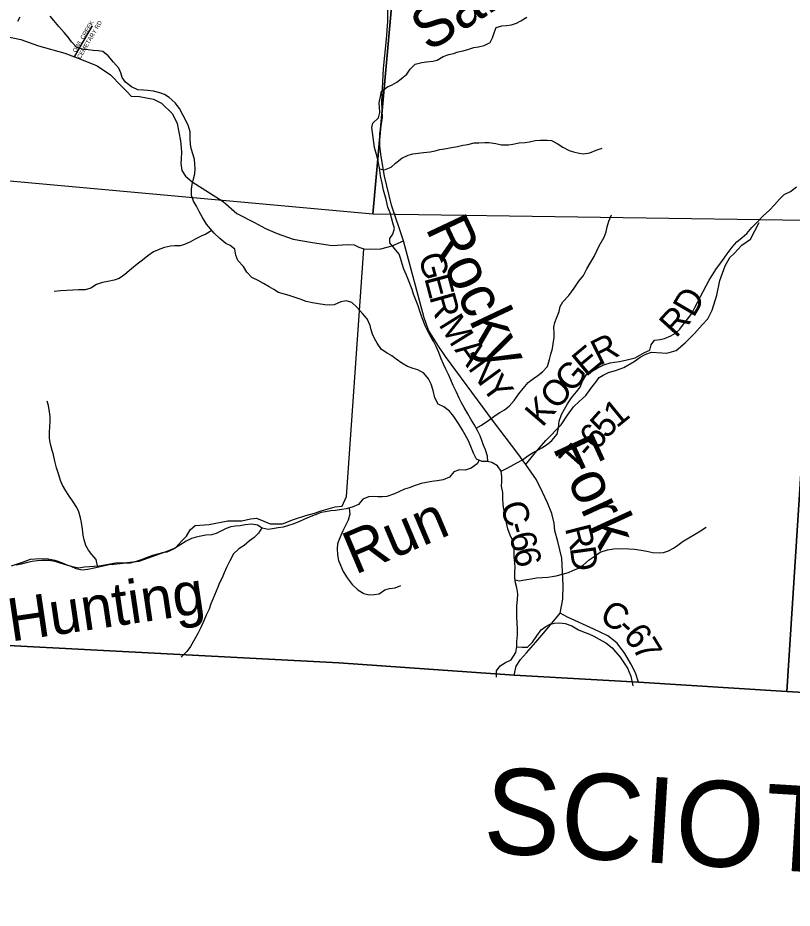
# Model space of a CAD drawing. Extents: x 1578669 to 1989827, y 208020 to 553079.
# Drawn here: x 1851077 to 1860103, y 344278 to 354659 of the extents above; entities that cross this region are included whole.
import ezdxf

# ---------------------------------------------------------------- set-up
doc = ezdxf.new("R2010")
doc.units = 0
for name, color, linetype in [('GM_X_Adjacent_County', 7, 'Continuous'), ('GM_X_Adjacent_County_Text', 7, 'Continuous'), ('GM_X_County', 7, 'Continuous'), ('GM_X_County_Road', 7, 'Continuous'), ('GM_X_County_Road_Text', 7, 'Continuous'), ('GM_X_Minor_River', 7, 'Continuous'), ('GM_X_Minor_River_Text', 7, 'Continuous'), ('GM_X_Section', 7, 'Continuous'), ('GM_X_Township', 7, 'Continuous'), ('GM_X_Township_Road', 7, 'Continuous'), ('GM_X_Township_Road_Text', 7, 'Continuous'), ('GM_X_Township_Subdivision', 7, 'Continuous'), ('GM_X_Township_Subdivision_Text', 7, 'Continuous')]:
    doc.layers.add(name, color=color, linetype=linetype)

msp = doc.modelspace()

# ---------------------------------------------------------------- linework, layer by layer
at = {"layer": 'GM_X_Adjacent_County'}
msp.add_lwpolyline([(1795056, 349285), (1813587, 349087), (1813935, 349079), (1818598, 348960), (1819510, 348957), (1826336, 348649), (1831370, 348458), (1833224, 348359), (1833481, 348350), (1833762, 348331), (1834882, 348273), (1835528, 348231), (1838968, 348044), (1844797, 347685), (1845155, 347665), (1846968, 347563), (1848416, 347480), (1849999, 347391), (1854820, 347140), (1856863, 346996), (1858312, 346913), (1860040, 346806), (1865771, 346465)], dxfattribs=at)
at = {"layer": 'GM_X_County'}
msp.add_lwpolyline([(1865771, 346465), (1860040, 346806), (1858312, 346913), (1856863, 346996), (1854820, 347140), (1849999, 347391), (1848416, 347480), (1846968, 347563), (1845155, 347665), (1844797, 347685), (1838968, 348044), (1835528, 348231), (1834882, 348273), (1833762, 348331), (1833481, 348350), (1833224, 348359), (1831370, 348458), (1826336, 348649), (1819510, 348957), (1818598, 348960), (1813935, 349079), (1813587, 349087), (1795056, 349285)], dxfattribs=at)
at = {"layer": 'GM_X_County_Road'}
for points in [[(1857398, 347719), (1857431, 347880), (1857432, 348039), (1857427, 348199), (1857419, 348360), (1857370, 348553), (1857335, 348677), (1857329, 348768), (1857302, 348880), (1857252, 349005), (1857193, 349129), (1857121, 349272), (1857000, 349450), (1856904, 349579), (1856620, 349951), (1856064, 350711), (1855973, 350842), (1855865, 351019), (1855814, 351160), (1855572, 352058), (1855432, 352474), (1855353, 352812), (1855312, 353041), (1855297, 353161), (1855296, 353312), (1855329, 353494), (1855322, 353679), (1855340, 354070), (1855374, 354411), (1855389, 354618), (1855391, 354752)], [(1850927, 354444), (1851114, 354405), (1851320, 354333), (1851626, 354249), (1851738, 354205), (1851820, 354172), (1852004, 354101), (1852156, 353996), (1852282, 353868), (1852349, 353800), (1852399, 353747), (1852497, 353743), (1852660, 353710), (1852752, 353663), (1852881, 353538), (1852933, 353429), (1852972, 353224), (1852987, 353098), (1852981, 353010), (1852977, 352962), (1852990, 352879), (1853032, 352813), (1853108, 352746), (1853471, 352519), (1853631, 352376), (1853837, 352273), (1853963, 352204), (1854101, 352145), (1854285, 352077), (1854513, 352038), (1854740, 352005), (1854920, 352018), (1854996, 352013), (1855052, 351987), (1855112, 351964), (1855193, 351960), (1855307, 351967), (1855439, 351999), (1855572, 352058)], [(1851004, 348269), (1851133, 348314), (1851227, 348348), (1851337, 348355), (1851432, 348351), (1851510, 348336), (1851588, 348310), (1851650, 348283), (1851698, 348265), (1851786, 348245), (1851854, 348258), (1852026, 348271), (1852221, 348306), (1852351, 348310), (1852490, 348325), (1852805, 348438), (1852914, 348481), (1852986, 348559), (1853043, 348617), (1853085, 348691), (1853145, 348739), (1853306, 348750), (1853525, 348793), (1853687, 348796), (1853789, 348819), (1853858, 348825), (1853946, 348792), (1854020, 348758), (1854162, 348761), (1854289, 348811), (1854433, 348856), (1854537, 348885), (1854614, 348909), (1854776, 348956), (1854857, 348966), (1854909, 349078), (1855112, 351964)], [(1856863, 346996), (1856884, 347098), (1856938, 347176), (1857007, 347257), (1857115, 347379), (1857210, 347490), (1857398, 347719)], [(1858312, 346913), (1858275, 347024), (1858223, 347127), (1858151, 347247), (1858062, 347368), (1857955, 347453), (1857791, 347533), (1857486, 347672), (1857398, 347719)]]:
    msp.add_lwpolyline(points, dxfattribs=at)
at = {"layer": 'GM_X_Minor_River'}
for points in [[(1851102, 354668), (1851073, 354616)], [(1853501, 352029), (1853432, 352085), (1853364, 352148), (1853278, 352254), (1853229, 352333), (1853192, 352400), (1853159, 352465), (1853124, 352520), (1853102, 352588), (1853101, 352662), (1853110, 352714), (1853123, 352768), (1853139, 352840), (1853144, 352898), (1853141, 352954), (1853138, 353008), (1853123, 353063), (1853098, 353137), (1853089, 353188), (1853087, 353254), (1853086, 353328), (1853065, 353395), (1853040, 353453), (1853006, 353520), (1852963, 353601), (1852912, 353668), (1852842, 353730), (1852786, 353767), (1852731, 353786), (1852659, 353805), (1852593, 353813), (1852541, 353814), (1852475, 353821), (1852404, 353854), (1852333, 353910), (1852292, 353965), (1852279, 354017), (1852254, 354072), (1852193, 354143), (1852130, 354217), (1852067, 354266), (1852015, 354275), (1851955, 354278), (1851899, 354285), (1851831, 354295), (1851770, 354310), (1851703, 354379), (1851664, 354434), (1851617, 354487), (1851554, 354559), (1851498, 354628), (1851454, 354679)], [(1856554, 349487), (1856551, 349548), (1856528, 349623), (1856505, 349675), (1856484, 349732), (1856467, 349784), (1856436, 349847), (1856397, 349916), (1856359, 349981), (1856324, 350040), (1856279, 350117), (1856250, 350169), (1856221, 350226), (1856189, 350295), (1856152, 350374), (1856123, 350440), (1856098, 350499), (1856066, 350564), (1856037, 350622), (1856012, 350683), (1855983, 350758), (1855953, 350826), (1855922, 350889), (1855885, 350954), (1855854, 351015), (1855825, 351069), (1855800, 351130), (1855781, 351181), (1855762, 351239), (1855742, 351300), (1855721, 351358), (1855690, 351439), (1855673, 351491), (1855631, 351600), (1855606, 351659), (1855578, 351730), (1855559, 351790), (1855540, 351845), (1855521, 351903), (1855466, 351968), (1855415, 352035), (1855414, 352086), (1855447, 352137), (1855469, 352201), (1855448, 352269), (1855431, 352326), (1855416, 352386), (1855391, 352453), (1855369, 352541), (1855354, 352594), (1855339, 352648), (1855323, 352733), (1855306, 352815), (1855292, 352910), (1855283, 352966), (1855270, 353022), (1855252, 353091), (1855235, 353147), (1855228, 353204), (1855219, 353264), (1855210, 353322), (1855205, 353380), (1855216, 353432), (1855281, 353493), (1855297, 353557), (1855292, 353617), (1855291, 353669), (1855304, 353741), (1855317, 353805), (1855386, 353856), (1855439, 353879), (1855496, 353910), (1855546, 353947), (1855613, 354004), (1855651, 354059), (1855710, 354120), (1855786, 354140), (1855842, 354147), (1855915, 354154), (1855967, 354165), (1856036, 354208), (1856102, 354230), (1856155, 354245), (1856211, 354262), (1856267, 354273), (1856336, 354294), (1856394, 354313), (1856446, 354322), (1856513, 354337), (1856581, 354371), (1856609, 354425), (1856628, 354483), (1856651, 354548), (1856717, 354565), (1856772, 354570), (1856832, 354579), (1856888, 354596), (1856941, 354623), (1857010, 354665)], [(1855294, 352899), (1855350, 352886), (1855428, 352919), (1855479, 352964), (1855554, 353021), (1855627, 353057), (1855680, 353074), (1855744, 353083), (1855806, 353090), (1855882, 353096), (1855943, 353109), (1855997, 353124), (1856049, 353133), (1856131, 353148), (1856202, 353158), (1856266, 353173), (1856322, 353184), (1856395, 353201), (1856449, 353203), (1856519, 353206), (1856569, 353205), (1856649, 353194), (1856715, 353180), (1856795, 353179), (1856847, 353186), (1856919, 353200), (1856989, 353207), (1857042, 353212), (1857108, 353227), (1857166, 353233), (1857246, 353234), (1857298, 353229), (1857362, 353193), (1857431, 353150), (1857502, 353111), (1857556, 353097), (1857620, 353080), (1857672, 353073), (1857746, 353086), (1857819, 353116), (1857887, 353139)], [(1856711, 349373), (1856772, 349403), (1856825, 349432), (1856895, 349469), (1856958, 349504), (1857023, 349551), (1857078, 349588), (1857132, 349615), (1857185, 349644), (1857250, 349689), (1857301, 349730), (1857364, 349803), (1857378, 349880), (1857387, 349958), (1857413, 350034), (1857448, 350096), (1857483, 350157), (1857529, 350228), (1857588, 350299), (1857633, 350354), (1857660, 350424), (1857704, 350499), (1857757, 350532), (1857830, 350575), (1857908, 350615), (1857981, 350636), (1858031, 350643), (1858089, 350654), (1858142, 350663), (1858196, 350674), (1858272, 350696), (1858329, 350725), (1858382, 350758), (1858442, 350785), (1858459, 350845), (1858497, 350902), (1858563, 350907), (1858613, 350920), (1858688, 350953), (1858742, 350984), (1858795, 351031), (1858836, 351086), (1858898, 351167), (1858939, 351220), (1858970, 351280), (1859002, 351349), (1859029, 351403), (1859064, 351468), (1859105, 351542), (1859137, 351599), (1859176, 351663), (1859221, 351736), (1859271, 351803), (1859310, 351856), (1859347, 351908), (1859404, 351985), (1859459, 352046), (1859521, 352097), (1859573, 352144), (1859633, 352213), (1859692, 352274), (1859764, 352350), (1859837, 352417), (1859896, 352478), (1859954, 352545), (1860011, 352598), (1860085, 352635), (1860155, 352687)], [(1856421, 349875), (1856483, 349910), (1856567, 349967), (1856642, 350021), (1856695, 350058), (1856749, 350089), (1856806, 350132), (1856861, 350197), (1856917, 350274), (1856968, 350337), (1857026, 350408), (1857087, 350455), (1857137, 350490), (1857194, 350533), (1857253, 350592), (1857273, 350676), (1857290, 350738), (1857309, 350804), (1857319, 350860), (1857328, 350932), (1857329, 350982), (1857324, 351052), (1857337, 351106), (1857365, 351177), (1857386, 351237), (1857397, 351295), (1857430, 351346), (1857498, 351423), (1857563, 351506), (1857617, 351589), (1857670, 351654), (1857710, 351732), (1857749, 351797), (1857795, 351878), (1857828, 351942), (1857855, 351999), (1857913, 352102), (1857936, 352164), (1857945, 352222), (1857965, 352288), (1857998, 352361)], [(1853337, 352181), (1853267, 352138), (1853213, 352113), (1853144, 352078), (1853089, 352047), (1853021, 352015), (1852970, 352002), (1852908, 351999), (1852856, 351996), (1852788, 351983), (1852731, 351960), (1852659, 351930), (1852592, 351885), (1852529, 351834), (1852470, 351787), (1852403, 351734), (1852325, 351668), (1852260, 351621), (1852202, 351600), (1852127, 351583), (1852065, 351572), (1851993, 351548), (1851928, 351507), (1851861, 351486), (1851785, 351488), (1851719, 351485), (1851649, 351478), (1851573, 351476), (1851501, 351467)], [(1856656, 346973), (1856656, 347044), (1856698, 347104), (1856760, 347141), (1856827, 347172), (1856883, 347259), (1856894, 347331), (1856895, 347387), (1856901, 347467), (1856900, 347533), (1856897, 347605), (1856895, 347670), (1856892, 347742), (1856895, 347802), (1856901, 347876), (1856904, 347944), (1856895, 348012), (1856880, 348071), (1856870, 348131), (1856871, 348199), (1856874, 348249), (1856869, 348303), (1856864, 348374), (1856863, 348424), (1856863, 348494), (1856848, 348560), (1856815, 348627), (1856790, 348702), (1856774, 348770), (1856761, 348821), (1856756, 348871), (1856743, 348929), (1856734, 348985), (1856731, 349054), (1856729, 349124), (1856714, 349200), (1856717, 349252), (1856720, 349306), (1856711, 349373), (1856670, 349436), (1856603, 349475), (1856551, 349488), (1856491, 349485), (1856424, 349515), (1856387, 349585), (1856357, 349662), (1856330, 349729), (1856291, 349798), (1856258, 349858), (1856214, 349930), (1856159, 350009), (1856108, 350072), (1856041, 350123), (1855978, 350155), (1855937, 350230), (1855917, 350314), (1855896, 350387), (1855865, 350449), (1855808, 350517), (1855739, 350556), (1855685, 350569), (1855620, 350593), (1855554, 350632), (1855487, 350681), (1855436, 350720), (1855383, 350750), (1855315, 350793), (1855265, 350864), (1855234, 350919), (1855213, 350969), (1855196, 351022), (1855183, 351072), (1855148, 351149), (1855095, 351212), (1855029, 351284), (1854970, 351341), (1854906, 351360), (1854842, 351347), (1854765, 351311), (1854709, 351308), (1854657, 351313), (1854581, 351326), (1854513, 351336), (1854439, 351353), (1854368, 351379), (1854310, 351400), (1854250, 351419), (1854187, 351436), (1854117, 351456), (1854060, 351491), (1854008, 351522), (1853941, 351560), (1853879, 351597), (1853804, 351632), (1853747, 351692), (1853708, 351761), (1853642, 351830), (1853617, 351893), (1853606, 351961), (1853553, 352004), (1853501, 352029)], [(1852010, 348252), (1851989, 348342), (1851940, 348401), (1851901, 348454), (1851870, 348506), (1851851, 348571), (1851840, 348627), (1851830, 348697), (1851821, 348774), (1851808, 348828), (1851787, 348899), (1851764, 348951), (1851724, 349014), (1851671, 349091), (1851638, 349144), (1851599, 349209), (1851574, 349264), (1851554, 349332), (1851527, 349411), (1851507, 349491), (1851494, 349562), (1851475, 349628), (1851460, 349687), (1851448, 349753), (1851447, 349823), (1851450, 349893), (1851455, 349949), (1851455, 350011), (1851448, 350066), (1851435, 350140), (1851420, 350190)], [(1856453, 349502), (1856431, 349458), (1856362, 349410), (1856291, 349385), (1856225, 349388), (1856161, 349367), (1856107, 349304), (1856035, 349272), (1855966, 349261), (1855904, 349254), (1855840, 349243), (1855780, 349229), (1855709, 349206), (1855637, 349179), (1855586, 349164), (1855520, 349134), (1855467, 349111), (1855378, 349080), (1855328, 349073), (1855274, 349076), (1855222, 349077), (1855166, 349074), (1855099, 349048), (1855048, 348985), (1854976, 348952), (1854905, 348935), (1854855, 348926), (1854779, 348916), (1854726, 348909), (1854664, 348900), (1854614, 348893), (1854543, 348866), (1854475, 348836), (1854420, 348813), (1854352, 348782), (1854281, 348757), (1854231, 348740), (1854170, 348719), (1854112, 348712), (1854044, 348702), (1853994, 348695), (1853926, 348708), (1853870, 348743), (1853803, 348757), (1853728, 348748), (1853670, 348735), (1853612, 348732), (1853560, 348725), (1853505, 348706), (1853453, 348679), (1853390, 348645), (1853336, 348630), (1853268, 348627), (1853211, 348616), (1853155, 348603), (1853103, 348588), (1853038, 348557), (1852967, 348509), (1852886, 348460), (1852815, 348429), (1852763, 348420), (1852707, 348404), (1852648, 348389), (1852584, 348366), (1852515, 348339), (1852457, 348320), (1852386, 348300), (1852336, 348299), (1852270, 348294), (1852196, 348287), (1852142, 348280), (1852086, 348270), (1852021, 348255), (1851967, 348242), (1851893, 348227), (1851824, 348219), (1851759, 348236), (1851701, 348261), (1851649, 348278), (1851572, 348302), (1851514, 348319), (1851440, 348330), (1851360, 348332), (1851302, 348329), (1851244, 348320), (1851192, 348309), (1851115, 348291), (1851057, 348278)], [(1854939, 348943), (1854946, 348872), (1854929, 348803), (1854891, 348733), (1854866, 348678), (1854831, 348598), (1854803, 348528), (1854798, 348468), (1854803, 348396), (1854815, 348332), (1854838, 348277), (1854869, 348203), (1854916, 348128), (1854976, 348052), (1855039, 347989), (1855110, 347949), (1855174, 347932), (1855232, 347935), (1855288, 347944), (1855355, 347989), (1855410, 348004), (1855476, 348014), (1855543, 348041)], [(1856874, 348106), (1856921, 348096), (1856987, 348107), (1857059, 348119), (1857124, 348130), (1857190, 348135), (1857254, 348139), (1857304, 348144), (1857354, 348152), (1857427, 348174), (1857495, 348193), (1857546, 348214), (1857614, 348243), (1857669, 348280), (1857736, 348340), (1857807, 348387), (1857866, 348428), (1857951, 348458), (1858025, 348469), (1858081, 348470), (1858199, 348467), (1858265, 348464), (1858341, 348451), (1858407, 348439), (1858477, 348426), (1858551, 348420), (1858605, 348427), (1858661, 348446), (1858718, 348477), (1858769, 348512), (1858834, 348557), (1858898, 348596), (1858965, 348635), (1859034, 348677), (1859101, 348722)], [(1853920, 348712), (1853881, 348651), (1853832, 348600), (1853779, 348561), (1853716, 348508), (1853653, 348467), (1853592, 348410), (1853550, 348329), (1853509, 348251), (1853483, 348188), (1853458, 348130), (1853429, 348073), (1853408, 348019), (1853349, 347880), (1853328, 347826), (1853309, 347766), (1853274, 347693), (1853244, 347629), (1853209, 347552), (1853175, 347479), (1853140, 347417), (1853090, 347328), (1853047, 347271), (1852982, 347205)], [(1856893, 347325), (1856954, 347322), (1857018, 347323), (1857077, 347379), (1857125, 347453), (1857176, 347522), (1857233, 347563), (1857283, 347588), (1857334, 347601), (1857386, 347604), (1857456, 347596), (1857533, 347569), (1857613, 347523), (1857678, 347496), (1857732, 347475), (1857791, 347450), (1857855, 347416), (1857932, 347371), (1858005, 347313), (1858046, 347262), (1858099, 347203), (1858136, 347148), (1858182, 347077), (1858224, 346983), (1858244, 346872)]]:
    msp.add_lwpolyline(points, dxfattribs=at)
at = {"layer": 'GM_X_Section'}
for points in [[(1850307, 358069), (1855700, 357766), (1855214, 352368), (1849954, 352849)], [(1855700, 357766), (1860738, 357233), (1860524, 352292), (1855214, 352368)]]:
    msp.add_lwpolyline(points, close=True, dxfattribs=at)
at = {"layer": 'GM_X_Township'}
for points in [[(1860651, 356303), (1860040, 346806), (1858312, 346913), (1856863, 346996), (1854820, 347140), (1849999, 347391), (1848416, 347480), (1846968, 347563), (1845155, 347665), (1844797, 347685), (1838968, 348044), (1839041, 349111), (1839441, 357011), (1839540, 358655), (1839593, 359479), (1839780, 362417), (1840250, 369801)], [(1865771, 346465), (1860040, 346806), (1860651, 356303)]]:
    msp.add_lwpolyline(points, dxfattribs=at)
at = {"layer": 'GM_X_Township_Road'}
msp.add_lwpolyline([(1857000, 349450), (1857107, 349587), (1857232, 349731), (1857411, 349913), (1857486, 350025), (1857555, 350125), (1857621, 350185), (1857696, 350256), (1857766, 350354), (1857813, 350410), (1857853, 350466), (1857899, 350492), (1857962, 350522), (1858056, 350551), (1858141, 350583), (1858261, 350653), (1858332, 350704), (1858396, 350738), (1858464, 350762), (1858584, 350753), (1858643, 350751), (1858749, 350782), (1858856, 350868), (1858966, 350980), (1859053, 351080), (1859118, 351151), (1859172, 351252), (1859225, 351424), (1859258, 351596), (1859323, 351766), (1859376, 351866), (1859426, 351910), (1859515, 352008), (1859618, 352080), (1859719, 352272)], dxfattribs=at)
at = {"layer": 'GM_X_Township_Subdivision'}
msp.add_lwpolyline([(1851738, 354205), (1851946, 354564)], dxfattribs=at)

# ---------------------------------------------------------------- texts
at = {"layer": 'GM_X_Adjacent_County_Text'}
msp.add_text('SCIOTO COUNTY', height=1000, rotation=356.533, dxfattribs=at).set_placement((1856488, 344929))
at = {"layer": 'GM_X_County_Road_Text'}
for s, rotation, p in [('G', 284.9781, (1855745, 351881)), ('E', 284.9816, (1855813, 351626)), ('R', 285.5173, (1855872, 351407)), ('M', 301.8274, (1855975, 351084)), ('A', 306.2088, (1856161, 350787)), ('N', 306.1297, (1856317, 350574)), ('Y', 306.1217, (1856472, 350361)), ('C', 286.3721, (1856698, 348979)), ('-', 286.1213, (1856767, 348743)), ('R', 284.2597, (1857452, 348709)), ('6', 285.3149, (1856801, 348626)), ('6', 283.1666, (1856849, 348450)), ('D', 277.7978, (1857511, 348479)), ('C', 330.8127, (1857841, 347629)), ('-', 317.6936, (1858040, 347521)), ('6', 309.3089, (1858122, 347447)), ('7', 301.2944, (1858232, 347314))]:
    msp.add_text(s, height=300, rotation=rotation, dxfattribs=at).set_placement(p)
at = {"layer": 'GM_X_Minor_River_Text'}
for s, rotation, p in [('Sand', 32.382, (1855866, 354254)), ('Rocky', 295.2863, (1855824, 352207)), ('Fork', 294.6859, (1857305, 349649)), ('Run', 22.9198, (1855008, 348163)), ('Hunting', 8.4088, (1850999, 347386))]:
    msp.add_text(s, height=500, rotation=rotation, dxfattribs=at).set_placement(p)
at = {"layer": 'GM_X_Township_Road_Text'}
for s, rotation, p in [('D', 59.6957, (1858954, 351154)), ('R', 47.7499, (1858748, 350917)), ('R', 26.6733, (1857855, 350600)), ('E', 39.8659, (1857698, 350466)), ('G', 49.0629, (1857534, 350275)), ('O', 49.2525, (1857362, 350076)), ('K', 49.2462, (1857190, 349876)), ('1', 39.2978, (1858058, 349869)), ('5', 47.9524, (1857943, 349740)), ('6', 50.3211, (1857827, 349601)), ('T', 48.4597, (1857591, 349332)), ('-', 49.146, (1857742, 349502))]:
    msp.add_text(s, height=300, rotation=rotation, dxfattribs=at).set_placement(p)
at = {"layer": 'GM_X_Township_Subdivision_Text'}
for s, rotation, p in [('OWL CREEK', 59.6415, (1851755, 354249)), ('CEMETARY RD', 59.5346, (1851807, 354175))]:
    msp.add_text(s, height=50, rotation=rotation, dxfattribs=at).set_placement(p)

doc.saveas('drawing.dxf')
